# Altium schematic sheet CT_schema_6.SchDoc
size 287 x 160 mm
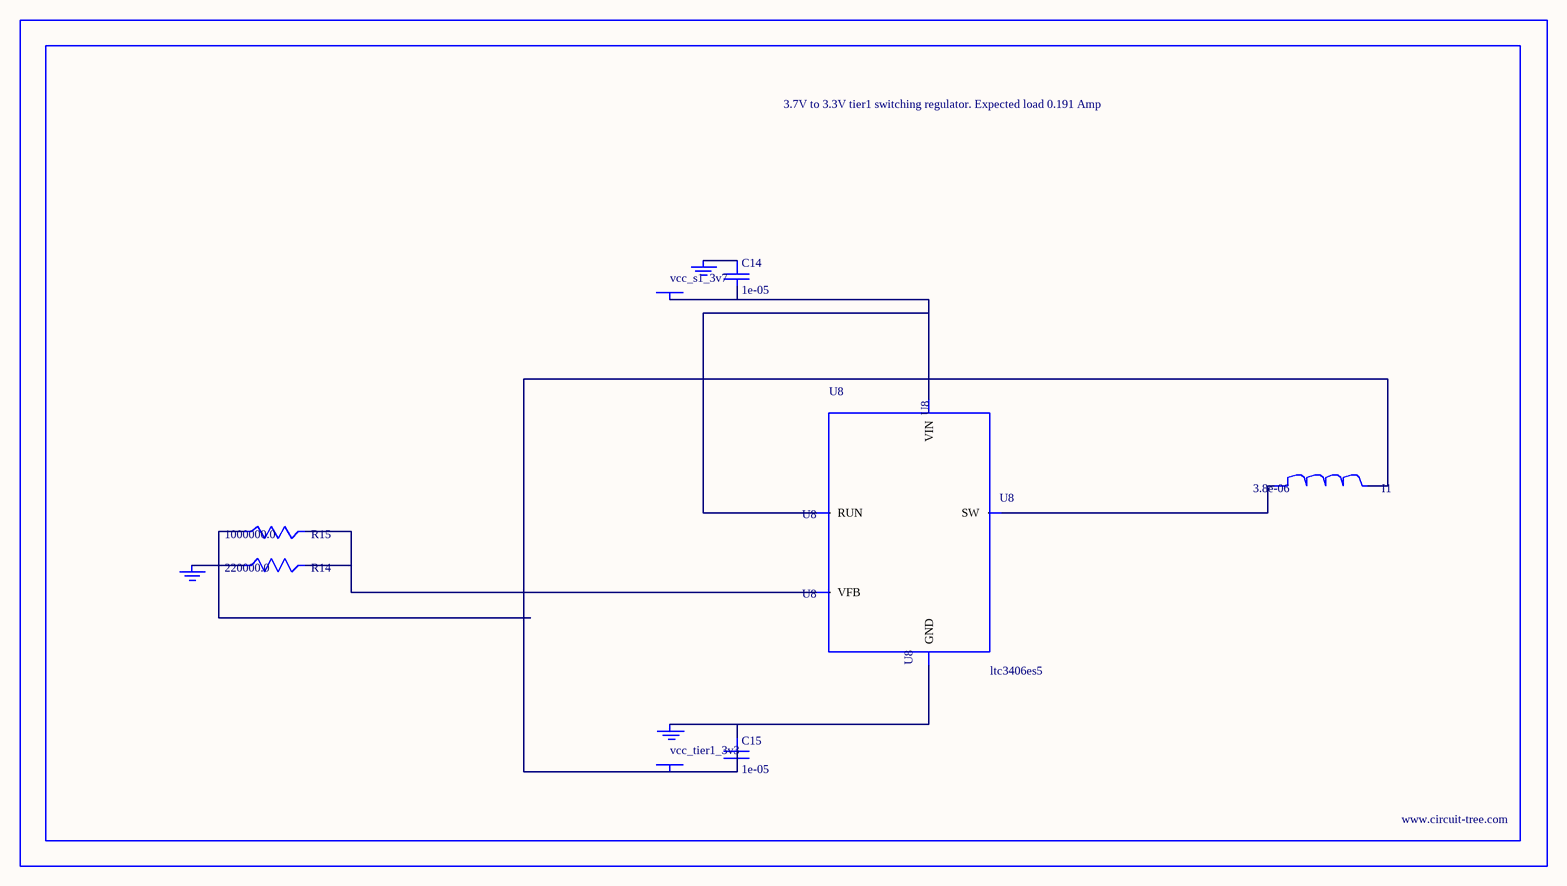
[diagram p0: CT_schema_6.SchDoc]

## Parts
BORDER5  (no value)
C14  1e-05  [C0805]
C15  1e-05  [C0805]
GND_INSTANCE_5_0  (no value)
GND_INSTANCE_5_1  (no value)
GND_INSTANCE_5_2  (no value)
I1  3.8e-06  [DR1040]
POWER_INSTANCE_5_0  vcc_tier1_3v3
POWER_INSTANCE_5_1  vcc_s1_3v7
R14  220000.0  [R0603]
R15  1000000.0  [R0603]
U8  ltc3406es5  [TSOT-23-5]

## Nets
NetC14_1: C14.1 GND_INSTANCE_5_1.0(GND)
NetC14_2: C14.2 POWER_INSTANCE_5_1.0(PWR) U8.1(RUN) U8.4(VIN)
NetC15_1: C15.1 GND_INSTANCE_5_0.0(GND) U8.2(GND)
NetC15_2: C15.2 I1.2 POWER_INSTANCE_5_0.0(PWR) R15.1
NetGND_INSTANCE_5_2_0: GND_INSTANCE_5_2.0(GND) R14.1
NetI1_1: I1.1 U8.3(SW)
NetR14_2: R14.2 R15.2 U8.5(VFB)

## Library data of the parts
BORDER5 = BORDER_PAGE5
C14 C15 = C0805C106K8RACTU
GND_INSTANCE_5_0-GND_INSTANCE_5_2 = GND
I1 = DR1040-3R8-R
POWER_INSTANCE_5_0 POWER_INSTANCE_5_1 = PWR
R14 = RC0603JR-07220KL
R15 = RC0603JR-071ML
